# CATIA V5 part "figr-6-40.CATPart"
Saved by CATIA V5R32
Part number: Part1
Bounding box of the stored display mesh (mm): x -40.3 to 40.3, y -45.975 to 45.975, z 0 to 40
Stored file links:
  D:\PROJECTS\Project 2022\CATIA V5 6R 2022\Resources\Part Files\c06_catia_v5_6r2022_prt\figr-6-40.CATPart
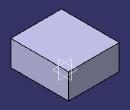
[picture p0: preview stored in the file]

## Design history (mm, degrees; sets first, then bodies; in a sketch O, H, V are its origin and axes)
Body1 (main body)
  Sketch1 on xy-plane, origin (0, 0, 0), H (1, 0, 0), V (0, 1, 0)
    line L1 (-40.2998, 45.9753) -> (40.2998, 45.9753)
    line L2 (40.2998, 45.9753) -> (40.2998, -45.9753)
    line L3 (40.2998, -45.9753) -> (-40.2998, -45.9753)
    line L4 (-40.2998, -45.9753) -> (-40.2998, 45.9753)
    axis line L5 (40.2998, -45.9753) -> (-40.2998, 45.9753)
    horizontal: L1 H, L3 H
    vertical: L2 V, L4 V
    midpoint: O L5
  Pad1: profile Sketch1, direction (0, 0, 1), length 40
